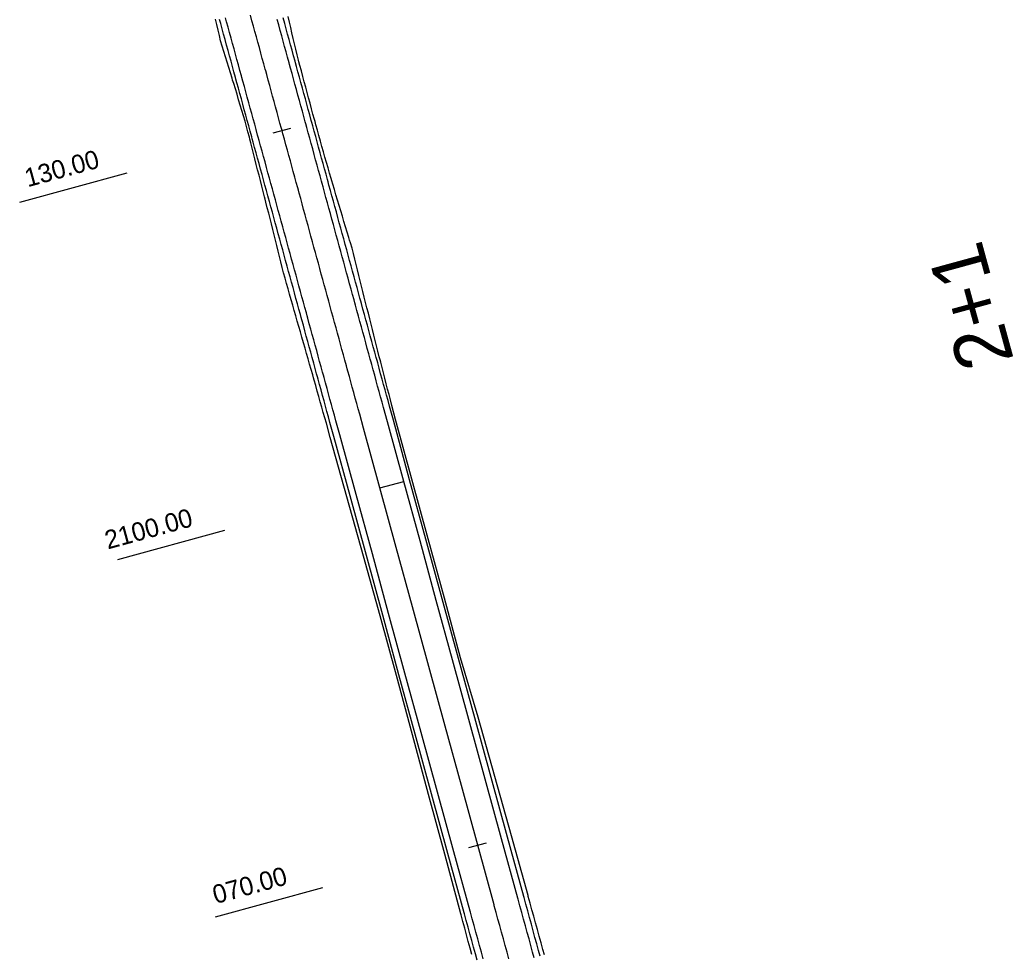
# Model space of a CAD drawing. Extents: x -550605 to -538780, y -1102367 to -1093705.
# Drawn here: x -547621.4 to -547541, y -1100221.4 to -1100145.7 of the extents above; entities that cross this region are included whole.
import ezdxf

# ---------------------------------------------------------------- set-up
doc = ezdxf.new("R2010")
doc.units = 0
for name, color, linetype in [('SIT - hrany vozovky', 7, 'Continuous'), ('SIT - osa cesty', 7, 'Continuous'), ('SIT - paty násypů', 7, 'Continuous'), ('SIT - staničení po 100m', 7, 'Continuous'), ('SIT - staničení po 30m', 7, 'Continuous')]:
    doc.layers.add(name, color=color, linetype=linetype)

msp = doc.modelspace()

# ---------------------------------------------------------------- linework, layer by layer
at = {"layer": 'SIT - hrany vozovky'}
for points in [[(-547584.372, -1100221.866), (-547584.519, -1100221.329), (-547584.666, -1100220.793), (-547584.813, -1100220.256), (-547584.96, -1100219.719), (-547585.107, -1100219.183), (-547585.254, -1100218.646), (-547585.4, -1100218.11), (-547585.423, -1100218.028), (-547586.743, -1100213.205), (-547588.063, -1100208.383), (-547589.383, -1100203.56), (-547590.703, -1100198.737), (-547592.023, -1100193.915), (-547593.343, -1100189.092), (-547594.662, -1100184.269), (-547595.982, -1100179.447), (-547596.295, -1100178.304), (-547596.415, -1100177.868), (-547596.534, -1100177.431), (-547596.654, -1100176.995), (-547596.773, -1100176.558), (-547596.893, -1100176.122), (-547597.012, -1100175.685), (-547597.131, -1100175.249), (-547597.251, -1100174.812), (-547597.302, -1100174.624), (-547597.37, -1100174.376), (-547597.49, -1100173.94), (-547597.609, -1100173.503), (-547597.729, -1100173.067), (-547597.848, -1100172.63), (-547597.968, -1100172.194), (-547598.087, -1100171.757), (-547598.207, -1100171.321), (-547598.326, -1100170.884), (-547598.445, -1100170.448), (-547598.565, -1100170.011), (-547598.622, -1100169.802), (-547598.684, -1100169.575), (-547598.804, -1100169.139), (-547598.923, -1100168.702), (-547599.043, -1100168.266), (-547599.162, -1100167.829), (-547599.282, -1100167.393), (-547599.401, -1100166.956), (-547599.521, -1100166.52), (-547599.64, -1100166.083), (-547599.759, -1100165.647), (-547599.879, -1100165.211), (-547599.942, -1100164.979), (-547599.998, -1100164.774), (-547600.118, -1100164.338), (-547600.237, -1100163.901), (-547600.357, -1100163.465), (-547600.476, -1100163.028), (-547600.596, -1100162.592), (-547600.715, -1100162.155), (-547600.835, -1100161.719), (-547600.954, -1100161.282), (-547601.074, -1100160.846), (-547601.193, -1100160.41), (-547601.262, -1100160.156), (-547601.312, -1100159.973), (-547601.432, -1100159.537), (-547601.551, -1100159.1), (-547601.671, -1100158.664), (-547601.79, -1100158.227), (-547601.91, -1100157.791), (-547602.029, -1100157.354), (-547602.149, -1100156.918), (-547602.268, -1100156.481), (-547602.388, -1100156.045), (-547602.507, -1100155.609), (-547602.582, -1100155.334), (-547602.626, -1100155.172), (-547602.746, -1100154.736), (-547602.865, -1100154.299), (-547602.985, -1100153.863), (-547603.104, -1100153.426), (-547603.224, -1100152.99), (-547603.343, -1100152.553), (-547603.463, -1100152.117), (-547603.582, -1100151.681), (-547603.702, -1100151.244), (-547603.821, -1100150.808), (-547603.902, -1100150.511), (-547603.94, -1100150.371), (-547604.06, -1100149.935), (-547604.179, -1100149.498), (-547604.299, -1100149.062), (-547604.418, -1100148.625), (-547604.538, -1100148.189), (-547604.657, -1100147.752), (-547604.777, -1100147.316), (-547604.896, -1100146.88), (-547605.016, -1100146.443), (-547605.135, -1100146.007), (-547605.222, -1100145.688)], [(-547583.89, -1100221.734), (-547584.037, -1100221.197), (-547584.184, -1100220.661), (-547584.331, -1100220.124), (-547584.478, -1100219.587), (-547584.624, -1100219.051), (-547584.771, -1100218.514), (-547584.918, -1100217.978), (-547584.941, -1100217.896), (-547586.26, -1100213.073), (-547587.58, -1100208.251), (-547588.9, -1100203.428), (-547590.22, -1100198.605), (-547591.54, -1100193.783), (-547592.86, -1100188.96), (-547594.18, -1100184.137), (-547595.5, -1100179.315), (-547595.813, -1100178.172), (-547595.932, -1100177.736), (-547596.052, -1100177.299), (-547596.171, -1100176.863), (-547596.291, -1100176.426), (-547596.41, -1100175.99), (-547596.53, -1100175.553), (-547596.649, -1100175.117), (-547596.769, -1100174.68), (-547596.82, -1100174.492), (-547596.888, -1100174.244), (-547597.008, -1100173.808), (-547597.127, -1100173.371), (-547597.246, -1100172.935), (-547597.366, -1100172.498), (-547597.485, -1100172.062), (-547597.605, -1100171.625), (-547597.724, -1100171.189), (-547597.844, -1100170.752), (-547597.963, -1100170.316), (-547598.083, -1100169.879), (-547598.14, -1100169.67), (-547598.202, -1100169.443), (-547598.322, -1100169.007), (-547598.441, -1100168.57), (-547598.56, -1100168.134), (-547598.68, -1100167.697), (-547598.799, -1100167.261), (-547598.919, -1100166.824), (-547599.038, -1100166.388), (-547599.158, -1100165.951), (-547599.277, -1100165.515), (-547599.397, -1100165.079), (-547599.46, -1100164.847), (-547599.516, -1100164.642), (-547599.636, -1100164.206), (-547599.755, -1100163.769), (-547599.874, -1100163.333), (-547599.994, -1100162.896), (-547600.113, -1100162.46), (-547600.233, -1100162.023), (-547600.352, -1100161.587), (-547600.472, -1100161.15), (-547600.591, -1100160.714), (-547600.711, -1100160.278), (-547600.78, -1100160.024), (-547600.83, -1100159.841), (-547600.95, -1100159.405), (-547601.069, -1100158.968), (-547601.189, -1100158.532), (-547601.308, -1100158.095), (-547601.427, -1100157.659), (-547601.547, -1100157.222), (-547601.666, -1100156.786), (-547601.786, -1100156.35), (-547601.905, -1100155.913), (-547602.025, -1100155.477), (-547602.1, -1100155.202), (-547602.144, -1100155.04), (-547602.264, -1100154.604), (-547602.383, -1100154.167), (-547602.503, -1100153.731), (-547602.622, -1100153.294), (-547602.741, -1100152.858), (-547602.861, -1100152.421), (-547602.98, -1100151.985), (-547603.1, -1100151.549), (-547603.219, -1100151.112), (-547603.339, -1100150.676), (-547603.42, -1100150.379), (-547603.458, -1100150.239), (-547603.578, -1100149.803), (-547603.697, -1100149.366), (-547603.817, -1100148.93), (-547603.936, -1100148.493), (-547604.055, -1100148.057), (-547604.175, -1100147.62), (-547604.294, -1100147.184), (-547604.414, -1100146.748), (-547604.533, -1100146.311), (-547604.653, -1100145.875), (-547604.74, -1100145.556)], [(-547579.762, -1100221.663), (-547579.885, -1100221.214), (-547580.032, -1100220.678), (-547580.179, -1100220.141), (-547580.326, -1100219.605), (-547580.473, -1100219.068), (-547580.619, -1100218.531), (-547580.766, -1100217.995), (-547580.913, -1100217.458), (-547581.06, -1100216.922), (-547581.082, -1100216.84), (-547582.402, -1100212.017), (-547583.722, -1100207.195), (-547585.042, -1100202.372), (-547586.362, -1100197.549), (-547587.682, -1100192.727), (-547589.002, -1100187.904), (-547590.322, -1100183.082), (-547591.642, -1100178.259), (-547591.955, -1100177.116), (-547592.074, -1100176.68), (-547592.194, -1100176.243), (-547592.313, -1100175.807), (-547592.433, -1100175.37), (-547592.552, -1100174.934), (-547592.672, -1100174.497), (-547592.791, -1100174.061), (-547592.911, -1100173.624), (-547592.962, -1100173.436), (-547593.03, -1100173.188), (-547593.149, -1100172.752), (-547593.269, -1100172.315), (-547593.388, -1100171.879), (-547593.508, -1100171.442), (-547593.627, -1100171.006), (-547593.747, -1100170.569), (-547593.866, -1100170.133), (-547593.986, -1100169.696), (-547594.105, -1100169.26), (-547594.225, -1100168.824), (-547594.282, -1100168.614), (-547594.344, -1100168.387), (-547594.463, -1100167.951), (-547594.583, -1100167.514), (-547594.702, -1100167.078), (-547594.822, -1100166.641), (-547594.941, -1100166.205), (-547595.061, -1100165.768), (-547595.18, -1100165.332), (-547595.3, -1100164.895), (-547595.419, -1100164.459), (-547595.539, -1100164.023), (-547595.602, -1100163.791), (-547595.658, -1100163.586), (-547595.777, -1100163.15), (-547595.897, -1100162.713), (-547596.016, -1100162.277), (-547596.136, -1100161.84), (-547596.255, -1100161.404), (-547596.375, -1100160.967), (-547596.494, -1100160.531), (-547596.614, -1100160.095), (-547596.733, -1100159.658), (-547596.853, -1100159.222), (-547596.922, -1100158.968), (-547596.972, -1100158.785), (-547597.092, -1100158.349), (-547597.211, -1100157.912), (-547597.33, -1100157.476), (-547597.45, -1100157.039), (-547597.569, -1100156.603), (-547597.689, -1100156.166), (-547597.808, -1100155.73), (-547597.928, -1100155.294), (-547598.047, -1100154.857), (-547598.167, -1100154.421), (-547598.242, -1100154.146), (-547598.286, -1100153.984), (-547598.406, -1100153.548), (-547598.525, -1100153.111), (-547598.644, -1100152.675), (-547598.764, -1100152.238), (-547598.883, -1100151.802), (-547599.003, -1100151.365), (-547599.122, -1100150.929), (-547599.242, -1100150.493), (-547599.361, -1100150.056), (-547599.481, -1100149.62), (-547599.562, -1100149.323), (-547599.6, -1100149.183), (-547599.72, -1100148.747), (-547599.839, -1100148.31), (-547599.958, -1100147.874), (-547600.078, -1100147.437), (-547600.197, -1100147.001), (-547600.317, -1100146.565), (-547600.436, -1100146.128), (-547600.556, -1100145.692)], [(-547579.28, -1100221.531), (-547579.403, -1100221.082), (-547579.55, -1100220.546), (-547579.697, -1100220.009), (-547579.843, -1100219.473), (-547579.99, -1100218.936), (-547580.137, -1100218.399), (-547580.284, -1100217.863), (-547580.431, -1100217.326), (-547580.578, -1100216.79), (-547580.6, -1100216.708), (-547581.92, -1100211.885), (-547583.24, -1100207.063), (-547584.56, -1100202.24), (-547585.88, -1100197.417), (-547587.2, -1100192.595), (-547588.52, -1100187.772), (-547589.84, -1100182.95), (-547591.16, -1100178.127), (-547591.473, -1100176.984), (-547591.592, -1100176.548), (-547591.712, -1100176.111), (-547591.831, -1100175.675), (-547591.95, -1100175.238), (-547592.07, -1100174.802), (-547592.189, -1100174.365), (-547592.309, -1100173.929), (-547592.428, -1100173.493), (-547592.48, -1100173.304), (-547592.548, -1100173.056), (-547592.667, -1100172.62), (-547592.787, -1100172.183), (-547592.906, -1100171.747), (-547593.026, -1100171.31), (-547593.145, -1100170.874), (-547593.264, -1100170.437), (-547593.384, -1100170.001), (-547593.503, -1100169.564), (-547593.623, -1100169.128), (-547593.742, -1100168.692), (-547593.8, -1100168.482), (-547593.862, -1100168.255), (-547593.981, -1100167.819), (-547594.101, -1100167.382), (-547594.22, -1100166.946), (-547594.34, -1100166.509), (-547594.459, -1100166.073), (-547594.578, -1100165.636), (-547594.698, -1100165.2), (-547594.817, -1100164.763), (-547594.937, -1100164.327), (-547595.056, -1100163.891), (-547595.12, -1100163.659), (-547595.176, -1100163.454), (-547595.295, -1100163.018), (-547595.415, -1100162.581), (-547595.534, -1100162.145), (-547595.654, -1100161.708), (-547595.773, -1100161.272), (-547595.893, -1100160.835), (-547596.012, -1100160.399), (-547596.131, -1100159.963), (-547596.251, -1100159.526), (-547596.37, -1100159.09), (-547596.44, -1100158.836), (-547596.49, -1100158.653), (-547596.609, -1100158.217), (-547596.729, -1100157.78), (-547596.848, -1100157.344), (-547596.968, -1100156.907), (-547597.087, -1100156.471), (-547597.207, -1100156.034), (-547597.326, -1100155.598), (-547597.445, -1100155.162), (-547597.565, -1100154.725), (-547597.684, -1100154.289), (-547597.76, -1100154.014), (-547597.804, -1100153.852), (-547597.923, -1100153.416), (-547598.043, -1100152.979), (-547598.162, -1100152.543), (-547598.282, -1100152.106), (-547598.401, -1100151.67), (-547598.521, -1100151.233), (-547598.64, -1100150.797), (-547598.759, -1100150.361), (-547598.879, -1100149.924), (-547598.998, -1100149.488), (-547599.08, -1100149.191), (-547599.118, -1100149.051), (-547599.237, -1100148.615), (-547599.357, -1100148.178), (-547599.476, -1100147.742), (-547599.596, -1100147.305), (-547599.715, -1100146.869), (-547599.835, -1100146.433), (-547599.954, -1100145.996), (-547600.074, -1100145.56)]]:
    msp.add_lwpolyline(points, dxfattribs=at)
at = {"layer": 'SIT - osa cesty'}
msp.add_lwpolyline([(-547581.814, -1100221.742), (-547581.961, -1100221.206), (-547582.108, -1100220.669), (-547582.255, -1100220.133), (-547582.402, -1100219.596), (-547582.549, -1100219.059), (-547582.695, -1100218.523), (-547582.842, -1100217.986), (-547582.989, -1100217.45), (-547583.011, -1100217.368), (-547584.331, -1100212.545), (-547585.651, -1100207.723), (-547586.971, -1100202.9), (-547588.291, -1100198.077), (-547589.611, -1100193.255), (-547590.931, -1100188.432), (-547592.251, -1100183.61), (-547593.571, -1100178.787), (-547593.884, -1100177.644), (-547594.003, -1100177.208), (-547594.123, -1100176.771), (-547594.242, -1100176.335), (-547594.362, -1100175.898), (-547594.481, -1100175.462), (-547594.601, -1100175.025), (-547594.72, -1100174.589), (-547594.84, -1100174.152), (-547594.891, -1100173.964), (-547594.959, -1100173.716), (-547595.078, -1100173.28), (-547595.198, -1100172.843), (-547595.317, -1100172.407), (-547595.437, -1100171.97), (-547595.556, -1100171.534), (-547595.676, -1100171.097), (-547595.795, -1100170.661), (-547595.915, -1100170.224), (-547596.034, -1100169.788), (-547596.154, -1100169.352), (-547596.211, -1100169.142), (-547596.273, -1100168.915), (-547596.393, -1100168.479), (-547596.512, -1100168.042), (-547596.631, -1100167.606), (-547596.751, -1100167.169), (-547596.87, -1100166.733), (-547596.99, -1100166.296), (-547597.109, -1100165.86), (-547597.229, -1100165.423), (-547597.348, -1100164.987), (-547597.468, -1100164.551), (-547597.531, -1100164.319), (-547597.587, -1100164.114), (-547597.707, -1100163.678), (-547597.826, -1100163.241), (-547597.945, -1100162.805), (-547598.065, -1100162.368), (-547598.184, -1100161.932), (-547598.304, -1100161.495), (-547598.423, -1100161.059), (-547598.543, -1100160.622), (-547598.662, -1100160.186), (-547598.782, -1100159.75), (-547598.851, -1100159.496), (-547598.901, -1100159.313), (-547599.021, -1100158.877), (-547599.14, -1100158.44), (-547599.259, -1100158.004), (-547599.379, -1100157.567), (-547599.498, -1100157.131), (-547599.618, -1100156.694), (-547599.737, -1100156.258), (-547599.857, -1100155.822), (-547599.976, -1100155.385), (-547600.096, -1100154.949), (-547600.171, -1100154.674), (-547600.215, -1100154.512), (-547600.335, -1100154.076), (-547600.454, -1100153.639), (-547600.574, -1100153.203), (-547600.693, -1100152.766), (-547600.812, -1100152.33), (-547600.932, -1100151.893), (-547601.051, -1100151.457), (-547601.171, -1100151.021), (-547601.29, -1100150.584), (-547601.41, -1100150.148), (-547601.491, -1100149.851), (-547601.529, -1100149.711), (-547601.649, -1100149.275), (-547601.768, -1100148.838), (-547601.888, -1100148.402), (-547602.007, -1100147.965), (-547602.126, -1100147.529), (-547602.246, -1100147.092), (-547602.365, -1100146.656), (-547602.485, -1100146.22), (-547602.604, -1100145.783), (-547602.724, -1100145.347)], dxfattribs=at)
at = {"layer": 'SIT - paty násypů'}
for points in [[(-547584.803, -1100221.407), (-547584.949, -1100220.87), (-547585.095, -1100220.333), (-547585.24, -1100219.796), (-547585.386, -1100219.259), (-547585.531, -1100218.722), (-547585.676, -1100218.185), (-547585.698, -1100218.103), (-547587.002, -1100213.276), (-547588.305, -1100208.449), (-547589.609, -1100203.622), (-547590.899, -1100198.791), (-547592.22, -1100193.969), (-547593.568, -1100189.154), (-547594.916, -1100184.339), (-547596.264, -1100179.524), (-547596.584, -1100178.383), (-547596.706, -1100177.947), (-547596.828, -1100177.512), (-547596.951, -1100177.076), (-547597.073, -1100176.64), (-547597.196, -1100176.205), (-547597.319, -1100175.769), (-547597.443, -1100175.334), (-547597.566, -1100174.899), (-547597.619, -1100174.711), (-547597.69, -1100174.463), (-547597.814, -1100174.028), (-547597.938, -1100173.593), (-547598.062, -1100173.158), (-547598.186, -1100172.723), (-547598.311, -1100172.288), (-547598.436, -1100171.853), (-547598.561, -1100171.418), (-547598.685, -1100170.983), (-547598.809, -1100170.547), (-547598.932, -1100170.112), (-547598.992, -1100169.903), (-547599.056, -1100169.677), (-547599.18, -1100169.241), (-547599.304, -1100168.806), (-547599.428, -1100168.371), (-547599.553, -1100167.936), (-547599.678, -1100167.501), (-547599.803, -1100167.066), (-547599.928, -1100166.631), (-547600.048, -1100166.195), (-547600.156, -1100165.756), (-547600.265, -1100165.316), (-547600.322, -1100165.083), (-547600.374, -1100164.877), (-547600.483, -1100164.437), (-547600.592, -1100163.998), (-547600.701, -1100163.559), (-547600.811, -1100163.12), (-547600.921, -1100162.681), (-547601.031, -1100162.242), (-547601.141, -1100161.803), (-547601.252, -1100161.364), (-547601.363, -1100160.925), (-547601.474, -1100160.486), (-547601.538, -1100160.232), (-547601.585, -1100160.048), (-547601.696, -1100159.609), (-547601.808, -1100159.17), (-547601.92, -1100158.732), (-547602.032, -1100158.293), (-547602.144, -1100157.855), (-547602.256, -1100157.417), (-547602.369, -1100156.978), (-547602.48, -1100156.54), (-547602.592, -1100156.101), (-547602.704, -1100155.662), (-547602.774, -1100155.386), (-547602.816, -1100155.224), (-547602.928, -1100154.785), (-547603.04, -1100154.347), (-547603.159, -1100153.91), (-547603.29, -1100153.477), (-547603.421, -1100153.044), (-547603.552, -1100152.611), (-547603.683, -1100152.177), (-547603.815, -1100151.744), (-547603.947, -1100151.311), (-547604.079, -1100150.878), (-547604.168, -1100150.584), (-547604.211, -1100150.445), (-547604.343, -1100150.012), (-547604.476, -1100149.579), (-547604.609, -1100149.147), (-547604.744, -1100148.715), (-547604.884, -1100148.284), (-547605.024, -1100147.853), (-547605.138, -1100147.415), (-547605.245, -1100146.975), (-547605.352, -1100146.535), (-547605.459, -1100146.095), (-547605.538, -1100145.775), (-547605.567, -1100145.656)], [(-547578.935, -1100221.436), (-547579.058, -1100220.988), (-547579.205, -1100220.451), (-547579.352, -1100219.915), (-547579.499, -1100219.378), (-547579.646, -1100218.842), (-547579.794, -1100218.305), (-547579.942, -1100217.769), (-547580.09, -1100217.233), (-547580.238, -1100216.696), (-547580.26, -1100216.615), (-547581.593, -1100211.796), (-547582.936, -1100206.979), (-547584.294, -1100202.167), (-547585.728, -1100197.376), (-547587.032, -1100192.549), (-547588.352, -1100187.726), (-547589.672, -1100182.904), (-547590.988, -1100178.08), (-547591.285, -1100176.933), (-547591.398, -1100176.495), (-547591.511, -1100176.056), (-547591.624, -1100175.618), (-547591.737, -1100175.18), (-547591.849, -1100174.741), (-547591.961, -1100174.303), (-547592.074, -1100173.865), (-547592.185, -1100173.426), (-547592.234, -1100173.237), (-547592.297, -1100172.987), (-547592.409, -1100172.549), (-547592.52, -1100172.11), (-547592.631, -1100171.671), (-547592.742, -1100171.233), (-547592.853, -1100170.794), (-547592.963, -1100170.355), (-547593.073, -1100169.916), (-547593.184, -1100169.477), (-547593.294, -1100169.038), (-547593.403, -1100168.599), (-547593.456, -1100168.388), (-547593.513, -1100168.16), (-547593.622, -1100167.72), (-547593.731, -1100167.281), (-547593.84, -1100166.842), (-547593.949, -1100166.402), (-547594.058, -1100165.963), (-547594.166, -1100165.524), (-547594.274, -1100165.084), (-547594.382, -1100164.644), (-547594.507, -1100164.209), (-547594.637, -1100163.776), (-547594.707, -1100163.546), (-547594.768, -1100163.342), (-547594.898, -1100162.909), (-547595.028, -1100162.475), (-547595.158, -1100162.042), (-547595.287, -1100161.608), (-547595.416, -1100161.174), (-547595.546, -1100160.74), (-547595.675, -1100160.307), (-547595.803, -1100159.873), (-547595.932, -1100159.439), (-547596.06, -1100159.005), (-547596.135, -1100158.753), (-547596.189, -1100158.571), (-547596.317, -1100158.137), (-547596.445, -1100157.702), (-547596.572, -1100157.268), (-547596.7, -1100156.834), (-547596.827, -1100156.4), (-547596.951, -1100155.965), (-547597.07, -1100155.528), (-547597.189, -1100155.091), (-547597.308, -1100154.655), (-547597.427, -1100154.218), (-547597.502, -1100153.943), (-547597.546, -1100153.782), (-547597.665, -1100153.345), (-547597.783, -1100152.908), (-547597.901, -1100152.471), (-547598.02, -1100152.035), (-547598.138, -1100151.598), (-547598.255, -1100151.161), (-547598.373, -1100150.724), (-547598.49, -1100150.287), (-547598.607, -1100149.85), (-547598.724, -1100149.413), (-547598.803, -1100149.116), (-547598.841, -1100148.975), (-547598.957, -1100148.538), (-547599.062, -1100148.098), (-547599.163, -1100147.656), (-547599.264, -1100147.215), (-547599.365, -1100146.773), (-547599.465, -1100146.331), (-547599.566, -1100145.89), (-547599.666, -1100145.448)]]:
    msp.add_lwpolyline(points, dxfattribs=at)
at = {"layer": 'SIT - staničení po 100m'}
msp.add_lwpolyline([(-547592.251, -1100183.61), (-547590.322, -1100183.082)], dxfattribs=at)
at = {"layer": 'SIT - staničení po 30m'}
for points in [[(-547600.894, -1100154.872), (-547599.448, -1100154.476)], [(-547621.39, -1100160.482), (-547612.71, -1100158.106)], [(-547613.471, -1100189.417), (-547604.79, -1100187.041)], [(-547585.055, -1100212.743), (-547583.608, -1100212.347)], [(-547605.551, -1100218.353), (-547596.87, -1100215.977)]]:
    msp.add_lwpolyline(points, dxfattribs=at)

# ---------------------------------------------------------------- texts
at = {"layer": 'SIT - staničení po 100m'}
msp.add_text('2+1', height=4.5, rotation=105.30701, dxfattribs=at).set_placement((-547540.915, -1100173.251))
at = {"layer": 'SIT - staničení po 30m'}
for s, p in [('130.00', (-547620.761, -1100159.273)), ('2100.00', (-547614.277, -1100188.601)), ('070.00', (-547605.548, -1100217.315))]:
    msp.add_text(s, height=1.5, rotation=15.30701, dxfattribs=at).set_placement(p)

doc.saveas('drawing.dxf')
